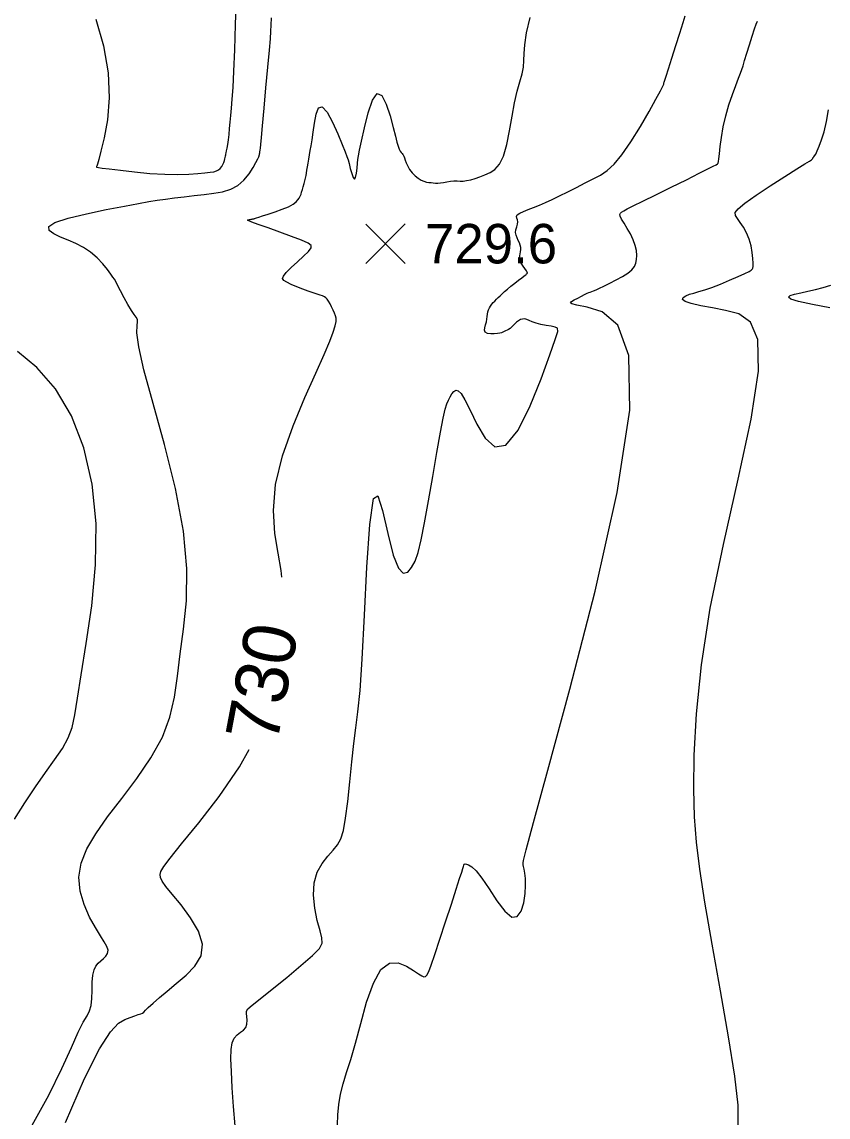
# Model space of a CAD drawing. Extents: x 2566142 to 2571431, y 418755 to 421584.
# Drawn here: x 2569336.6 to 2569642.8, y 419170.9 to 419587 of the extents above; entities that cross this region are included whole.
import ezdxf

# ---------------------------------------------------------------- set-up
doc = ezdxf.new("R2010")
doc.units = 0
for name, color, linetype in [('Contour_ADS_Label_Major', 7, 'Continuous'), ('Contour_ADS_Major', 7, 'Continuous'), ('Contour_ADS_Minor', 7, 'Continuous'), ('Contour_ADS_Spot_Elevation', 7, 'Continuous')]:
    doc.layers.add(name, color=color, linetype=linetype)

# ---------------------------------------------------------------- blocks, each defined once
blk = doc.blocks.new('S750')
at = {"layer": 'Contour_ADS_Spot_Elevation'}
for p, q in [((-0.5, 0.498), (0.5, -0.498)), ((-0.498, -0.5), (0.498, 0.5))]:
    blk.add_line(p, q, dxfattribs=at)

msp = doc.modelspace()

# ---------------------------------------------------------------- linework, layer by layer
at = {"layer": 'Contour_ADS_Major'}
for points in [[(2569449.32, 419554.31), (2569450.68, 419554.75), (2569452.5, 419552.7), (2569454.55, 419548.9), (2569456.55, 419544.45), (2569458.21, 419540.43), (2569459.34, 419537.67), (2569460.03, 419535.9), (2569460.48, 419534.58), (2569460.87, 419533.18), (2569461.34, 419531.34), (2569461.88, 419529.4), (2569462.44, 419527.86), (2569462.94, 419527.24), (2569463.34, 419527.89), (2569463.65, 419529.46), (2569463.88, 419531.42), (2569464.06, 419533.27), (2569464.21, 419534.68), (2569464.44, 419536.12), (2569464.86, 419538.23), (2569465.58, 419541.69), (2569466.69, 419546.79), (2569468.12, 419552.45), (2569469.76, 419557.25), (2569471.51, 419559.75), (2569473.27, 419558.97), (2569474.94, 419555.73), (2569476.42, 419551.27), (2569477.62, 419546.88), (2569478.48, 419543.54), (2569479.07, 419541.25), (2569479.49, 419539.72), (2569479.85, 419538.69), (2569480.23, 419537.92), (2569480.61, 419537.34), (2569480.97, 419536.93), (2569481.25, 419536.64), (2569481.44, 419536.45), (2569481.58, 419536.24), (2569481.72, 419535.92), (2569481.9, 419535.36), (2569482.17, 419534.5), (2569482.57, 419533.39), (2569483.13, 419532.15), (2569483.87, 419530.87), (2569484.82, 419529.65), (2569485.91, 419528.55), (2569487.07, 419527.62), (2569488.21, 419526.9), (2569489.27, 419526.43), (2569490.26, 419526.15), (2569491.17, 419526), (2569492.01, 419525.91), (2569492.82, 419525.83), (2569493.63, 419525.76), (2569494.52, 419525.75), (2569495.55, 419525.82), (2569496.74, 419525.99), (2569498.05, 419526.21), (2569499.39, 419526.42), (2569500.68, 419526.55), (2569501.86, 419526.57), (2569503, 419526.53), (2569504.19, 419526.53), (2569505.52, 419526.67), (2569507.05, 419526.99), (2569508.76, 419527.5), (2569510.59, 419528.14), (2569512.49, 419528.87), (2569514.41, 419529.71), (2569516.26, 419530.95), (2569517.98, 419532.94), (2569519.49, 419536.03), (2569520.74, 419540.41), (2569521.8, 419545.64), (2569522.77, 419551.13), (2569523.74, 419556.28), (2569524.76, 419560.62), (2569525.75, 419564.21), (2569526.58, 419567.22), (2569527.12, 419569.84), (2569527.3, 419572.28), (2569527.35, 419574.95), (2569527.58, 419578.3), (2569528.26, 419582.78), (2569529.64, 419588.64)], [(2569435.34, 419376.06), (2569435.12, 419378.57), (2569433.96, 419385.12), (2569432.72, 419392.67), (2569432.13, 419401.32), (2569432.93, 419411.17), (2569435.62, 419422.15), (2569439.63, 419433.49), (2569444.12, 419444.26), (2569448.25, 419453.52), (2569451.39, 419460.57), (2569453.53, 419465.62), (2569454.89, 419469.12), (2569455.65, 419471.5), (2569455.98, 419473.17), (2569455.99, 419474.38), (2569455.75, 419475.37), (2569455.33, 419476.34), (2569454.81, 419477.47), (2569454.23, 419478.68), (2569453.65, 419479.85), (2569453.09, 419480.86), (2569452.6, 419481.61), (2569452.1, 419482.15), (2569451.54, 419482.55), (2569450.82, 419482.88), (2569449.88, 419483.2), (2569448.69, 419483.58), (2569447.2, 419484.05), (2569445.39, 419484.66), (2569443.27, 419485.45), (2569441.04, 419486.34), (2569438.94, 419487.24), (2569437.22, 419488.06), (2569436.09, 419488.76), (2569435.64, 419489.48), (2569435.93, 419490.41), (2569437.03, 419491.75), (2569438.92, 419493.61), (2569441.23, 419495.77), (2569443.54, 419497.93), (2569445.41, 419499.78), (2569446.44, 419501.1), (2569446.45, 419502.08), (2569445.29, 419502.97), (2569442.82, 419504.05), (2569439.05, 419505.49), (2569434.56, 419507.13), (2569430.09, 419508.74), (2569426.39, 419510.06), (2569423.99, 419510.92), (2569422.74, 419511.39), (2569422.31, 419511.6), (2569422.33, 419511.68), (2569422.53, 419511.75), (2569422.8, 419511.81), (2569423.11, 419511.88), (2569423.42, 419511.94), (2569423.68, 419511.99), (2569423.91, 419512.03), (2569424.12, 419512.07), (2569424.32, 419512.1), (2569424.52, 419512.14), (2569424.71, 419512.18), (2569424.91, 419512.23), (2569425.09, 419512.28), (2569425.31, 419512.36), (2569425.72, 419512.5), (2569426.55, 419512.78), (2569428.01, 419513.25), (2569430.19, 419513.94), (2569432.83, 419514.81), (2569435.51, 419515.78), (2569437.87, 419516.77), (2569439.59, 419517.72), (2569440.74, 419518.58), (2569441.46, 419519.35), (2569441.91, 419520), (2569442.21, 419520.53), (2569442.44, 419521.03), (2569442.64, 419521.58), (2569442.86, 419522.3), (2569443.14, 419523.25), (2569443.46, 419524.37), (2569443.79, 419525.53), (2569444.08, 419526.66), (2569444.32, 419527.66), (2569444.53, 419528.59), (2569444.71, 419529.55), (2569444.89, 419530.63), (2569445.09, 419531.89), (2569445.3, 419533.3), (2569445.54, 419534.83), (2569445.81, 419536.42), (2569446.1, 419538.07), (2569446.43, 419539.93), (2569446.79, 419542.2), (2569447.21, 419545.08), (2569447.7, 419548.57), (2569448.37, 419551.95), (2569449.32, 419554.31)], [(2569353.19, 419168.77), (2569360.43, 419185.57), (2569366.08, 419196.85), (2569370.26, 419203.33), (2569373.35, 419206.52), (2569375.75, 419207.91), (2569377.77, 419208.77), (2569379.46, 419209.38), (2569380.8, 419209.82), (2569381.75, 419210.14), (2569382.36, 419210.42), (2569382.86, 419210.8), (2569383.52, 419211.45), (2569384.63, 419212.52), (2569386.41, 419214.14), (2569388.84, 419216.26), (2569391.81, 419218.79), (2569395.24, 419221.65), (2569398.94, 419224.77), (2569402.3, 419228.23), (2569404.64, 419232.12), (2569405.26, 419236.55), (2569403.73, 419241.51), (2569400.69, 419246.65), (2569397.04, 419251.48), (2569393.68, 419255.55), (2569391.33, 419258.51), (2569389.93, 419260.55), (2569389.28, 419261.97), (2569389.13, 419263.06), (2569389.38, 419264.19), (2569390.46, 419266.03), (2569392.91, 419269.28), (2569397.26, 419274.68), (2569403.78, 419282.67), (2569411.51, 419292.69), (2569419.23, 419303.91), (2569422.94, 419310.56)]]:
    msp.add_lwpolyline(points, dxfattribs=at)
at = {"layer": 'Contour_ADS_Minor'}
for points in [[(2569364.71, 419587.98), (2569367.63, 419577.85), (2569369.42, 419567.58), (2569369.79, 419558.11), (2569369.12, 419549.82), (2569367.9, 419542.99), (2569366.65, 419537.88), (2569365.79, 419534.65), (2569365.3, 419532.93), (2569365.08, 419532.23), (2569365, 419532.04), (2569364.98, 419531.95), (2569364.99, 419531.89), (2569365.01, 419531.84), (2569365.04, 419531.79), (2569365.15, 419531.75), (2569365.68, 419531.65), (2569367.08, 419531.46), (2569369.78, 419531.11), (2569374.03, 419530.59), (2569379.39, 419529.99), (2569385.21, 419529.44), (2569390.86, 419529.07), (2569395.82, 419528.98), (2569400, 419529.1), (2569403.41, 419529.35), (2569406.1, 419529.62), (2569408.09, 419529.85), (2569409.53, 419530.07), (2569410.56, 419530.35), (2569411.32, 419530.75), (2569411.96, 419531.31), (2569412.49, 419532), (2569412.93, 419532.76), (2569413.27, 419533.53), (2569413.53, 419534.27), (2569413.72, 419534.93), (2569413.85, 419535.49), (2569413.94, 419535.91), (2569413.99, 419536.19), (2569414.04, 419536.41), (2569414.1, 419536.71), (2569414.19, 419537.2), (2569414.35, 419537.97), (2569414.55, 419539.06), (2569414.78, 419540.46), (2569415.02, 419542.17), (2569415.27, 419544.18), (2569415.51, 419546.44), (2569415.76, 419548.9), (2569416, 419551.48), (2569416.25, 419554.23), (2569416.51, 419557.59), (2569416.79, 419562.08), (2569417.09, 419568.25), (2569417.43, 419576.4), (2569417.77, 419586), (2569418.1, 419596.29)], [(2569380.55, 419473.08), (2569380.47, 419473.97), (2569380.05, 419474.78), (2569379.29, 419475.8), (2569378.22, 419477.33), (2569376.87, 419479.55), (2569375.42, 419482.18), (2569374.05, 419484.77), (2569372.95, 419486.9), (2569372.24, 419488.3), (2569371.73, 419489.22), (2569371.2, 419490.05), (2569370.38, 419491.19), (2569369.08, 419492.92), (2569367.33, 419495.08), (2569365.18, 419497.38), (2569362.71, 419499.52), (2569360, 419501.3), (2569357.13, 419502.76), (2569354.21, 419504.03), (2569351.33, 419505.24), (2569348.7, 419506.48), (2569346.96, 419507.79), (2569346.85, 419509.21), (2569349.13, 419510.75), (2569354.19, 419512.41), (2569361.12, 419514.09), (2569368.65, 419515.65), (2569375.54, 419516.98), (2569380.84, 419517.98), (2569384.81, 419518.7), (2569388.05, 419519.24), (2569391.15, 419519.69), (2569394.57, 419520.12), (2569398.27, 419520.55), (2569402.1, 419520.97), (2569405.89, 419521.4), (2569409.5, 419521.85), (2569412.86, 419522.46), (2569415.93, 419523.42), (2569418.64, 419524.87), (2569420.96, 419526.91), (2569422.88, 419529.28), (2569424.39, 419531.61), (2569425.48, 419533.58), (2569426.17, 419534.91), (2569426.55, 419535.68), (2569426.7, 419536.06), (2569426.75, 419536.22), (2569426.76, 419536.31), (2569426.78, 419536.38), (2569426.8, 419536.48), (2569426.83, 419536.63), (2569426.88, 419536.88), (2569426.94, 419537.22), (2569427.01, 419537.67), (2569427.09, 419538.21), (2569427.18, 419538.95), (2569427.32, 419540.37), (2569427.57, 419543.04), (2569427.98, 419547.55), (2569428.59, 419554.17), (2569429.3, 419561.97), (2569430.01, 419569.73), (2569430.59, 419576.22), (2569430.97, 419580.58), (2569431.18, 419583.42), (2569431.29, 419585.73), (2569431.36, 419588.47)], [(2569586.47, 419582.74), (2569587.72, 419586.72), (2569588.56, 419589.32)], [(2569568.82, 419517.08), (2569572.39, 419518.86), (2569577.4, 419521.34), (2569583.2, 419524.2), (2569588.96, 419527.04), (2569593.83, 419529.45), (2569597.18, 419531.1), (2569599.19, 419532.12), (2569600.25, 419532.7), (2569600.75, 419533.04), (2569601.02, 419533.37), (2569601.18, 419533.93), (2569601.32, 419535), (2569601.51, 419536.82), (2569601.82, 419539.58), (2569602.3, 419543.09), (2569602.99, 419547.1), (2569603.93, 419551.33), (2569605.13, 419555.52), (2569606.44, 419559.44), (2569607.71, 419562.87), (2569608.76, 419565.58), (2569609.49, 419567.47), (2569610, 419568.9), (2569610.48, 419570.35), (2569611.08, 419572.3), (2569611.92, 419575.07), (2569612.93, 419578.33), (2569613.95, 419581.57), (2569614.84, 419584.3), (2569615.49, 419586.14), (2569615.94, 419587.25)], [(2569522.65, 419471.08), (2569522.07, 419470.55), (2569521.47, 419470.15), (2569520.86, 419469.83), (2569520.27, 419469.58), (2569519.73, 419469.36), (2569519.26, 419469.13), (2569518.75, 419468.91), (2569518.1, 419468.7), (2569517.2, 419468.54), (2569515.99, 419468.44), (2569514.66, 419468.45), (2569513.45, 419468.65), (2569512.6, 419469.11), (2569512.28, 419469.85), (2569512.38, 419470.81), (2569512.69, 419471.89), (2569513.03, 419473.01), (2569513.24, 419474.07), (2569513.36, 419475.07), (2569513.45, 419476), (2569513.58, 419476.85), (2569513.81, 419477.63), (2569514.15, 419478.35), (2569514.58, 419479.03), (2569515.08, 419479.68), (2569515.64, 419480.31), (2569516.24, 419480.94), (2569516.88, 419481.58), (2569517.54, 419482.24), (2569518.22, 419482.93), (2569518.98, 419483.68), (2569519.88, 419484.53), (2569521, 419485.5), (2569522.36, 419486.61), (2569523.83, 419487.77), (2569525.24, 419488.85), (2569526.42, 419489.76), (2569527.24, 419490.4), (2569527.76, 419490.81), (2569528.08, 419491.07), (2569528.29, 419491.23), (2569528.47, 419491.38), (2569528.57, 419491.58), (2569528.52, 419491.91), (2569528.23, 419492.45), (2569527.67, 419493.25), (2569526.96, 419494.23), (2569526.28, 419495.29), (2569525.79, 419496.32), (2569525.6, 419497.26), (2569525.66, 419498.1), (2569525.84, 419498.89), (2569526.02, 419499.67), (2569526.1, 419500.46), (2569526.07, 419501.27), (2569525.9, 419502.12), (2569525.58, 419503.01), (2569525.14, 419503.93), (2569524.67, 419504.9), (2569524.29, 419505.91), (2569524.13, 419506.96), (2569524.26, 419508.04), (2569524.57, 419509.11), (2569524.86, 419510.12), (2569524.98, 419511.03), (2569524.81, 419511.79), (2569524.54, 419512.45), (2569524.44, 419513.05), (2569524.75, 419513.65), (2569525.66, 419514.27), (2569527.1, 419514.95), (2569528.92, 419515.69), (2569530.97, 419516.49), (2569533.14, 419517.38), (2569535.47, 419518.39), (2569538.01, 419519.55), (2569540.83, 419520.9), (2569543.96, 419522.45), (2569547.25, 419524.12), (2569550.52, 419525.79), (2569553.58, 419527.35), (2569556.32, 419528.79), (2569558.9, 419530.48), (2569561.55, 419532.88), (2569564.52, 419536.46), (2569567.93, 419541.45), (2569571.49, 419547.22), (2569574.78, 419552.91), (2569577.41, 419557.63), (2569579.1, 419560.76), (2569579.98, 419562.53), (2569580.35, 419563.38), (2569580.46, 419563.77), (2569580.56, 419564.14), (2569580.81, 419564.89), (2569581.3, 419566.41), (2569582.16, 419569.1), (2569583.44, 419573.14), (2569584.96, 419577.96), (2569586.47, 419582.74)], [(2569614.06, 419493.12), (2569614.21, 419493.43), (2569614.33, 419494.1), (2569614.37, 419495.29), (2569614.27, 419497.1), (2569614, 419499.37), (2569613.52, 419501.9), (2569612.78, 419504.45), (2569611.78, 419506.83), (2569610.63, 419508.96), (2569609.45, 419510.79), (2569608.39, 419512.27), (2569607.64, 419513.41), (2569607.56, 419514.52), (2569608.6, 419515.96), (2569611.18, 419518.09), (2569615.5, 419521.13), (2569620.85, 419524.68), (2569626.3, 419528.2), (2569630.91, 419531.12), (2569633.97, 419533.05), (2569635.69, 419534.11), (2569636.47, 419534.61), (2569636.74, 419534.81), (2569636.87, 419534.96), (2569636.95, 419535.12), (2569637.03, 419535.28), (2569637.15, 419535.46), (2569637.34, 419535.68), (2569637.64, 419536.08), (2569638.08, 419536.79), (2569638.67, 419537.97), (2569639.44, 419539.73), (2569640.32, 419542.15), (2569641.25, 419545.25), (2569642.14, 419549.08), (2569642.95, 419553.63)], [(2569461.52, 419192.74), (2569463.31, 419198.92), (2569465.31, 419206.49), (2569467.55, 419214.51), (2569470.09, 419221.76), (2569472.98, 419227.01), (2569476.21, 419229.4), (2569479.54, 419229.5), (2569482.68, 419228.26), (2569485.3, 419226.6), (2569487.2, 419225.3), (2569488.48, 419224.5), (2569489.32, 419224.15), (2569489.92, 419224.24), (2569490.46, 419224.8), (2569491.11, 419226.15), (2569492.03, 419228.65), (2569493.4, 419232.7), (2569495.31, 419238.43), (2569497.52, 419245.11), (2569499.72, 419251.78), (2569501.58, 419257.48), (2569502.87, 419261.48), (2569503.66, 419263.96), (2569504.09, 419265.38), (2569504.31, 419266.15), (2569504.45, 419266.64), (2569504.62, 419266.94), (2569504.92, 419267.06), (2569505.43, 419267.02), (2569506.26, 419266.77), (2569507.47, 419266.02), (2569509.13, 419264.44), (2569511.32, 419261.67), (2569514.03, 419257.6), (2569517.03, 419253.06), (2569520, 419249.13), (2569522.65, 419246.87), (2569524.72, 419247.04), (2569526.22, 419249.13), (2569527.21, 419252.33), (2569527.75, 419255.83), (2569527.91, 419258.93), (2569527.81, 419261.51), (2569527.57, 419263.57), (2569527.31, 419265.08), (2569527.13, 419266.1), (2569527.03, 419266.73), (2569526.99, 419267.13), (2569526.98, 419267.45), (2569527.12, 419268.35), (2569528.16, 419272.44), (2569530.95, 419282.85), (2569536.37, 419302.69), (2569544.77, 419333.53), (2569554.33, 419370.74), (2569562.7, 419408.13), (2569567.51, 419439.53), (2569567.16, 419460.25), (2569562.96, 419471.72), (2569556.97, 419476.86), (2569551.24, 419478.59), (2569547.4, 419479.38), (2569545.44, 419479.88), (2569544.9, 419480.26), (2569545.35, 419480.7), (2569546.36, 419481.33), (2569547.69, 419482.08), (2569549.09, 419482.83), (2569550.34, 419483.46), (2569551.26, 419483.89), (2569551.92, 419484.16), (2569552.47, 419484.35), (2569553.02, 419484.55), (2569553.71, 419484.82), (2569554.65, 419485.23), (2569555.92, 419485.82), (2569557.64, 419486.64), (2569559.84, 419487.7), (2569562.3, 419488.94), (2569564.7, 419490.26), (2569566.77, 419491.57), (2569568.27, 419492.8), (2569569.25, 419494), (2569569.81, 419495.26), (2569570.09, 419496.67), (2569570.15, 419498.29), (2569569.99, 419500.1), (2569569.56, 419502.09), (2569568.8, 419504.2), (2569567.72, 419506.4), (2569566.49, 419508.55), (2569565.29, 419510.48), (2569564.35, 419512.04), (2569563.82, 419513.12), (2569563.68, 419513.83), (2569563.89, 419514.31), (2569564.38, 419514.71), (2569565.16, 419515.19), (2569566.52, 419515.92), (2569568.82, 419517.08)], [(2569608.7, 419167.96), (2569608.65, 419175.47), (2569607.33, 419186.42), (2569604.94, 419201.42), (2569601.91, 419218.87), (2569598.77, 419236.63), (2569596, 419252.55), (2569594.02, 419265.12), (2569592.77, 419275.37), (2569592.1, 419284.94), (2569591.86, 419295.5), (2569591.98, 419308.44), (2569592.77, 419324.14), (2569594.66, 419342.71), (2569598.05, 419364.26), (2569603.07, 419388.46), (2569608.68, 419413.23), (2569613.53, 419436.02), (2569616.32, 419454.31), (2569616.07, 419466.28), (2569613.31, 419472.96), (2569608.95, 419476.07), (2569603.87, 419477.36), (2569598.89, 419478.29), (2569594.44, 419479.14), (2569590.85, 419479.95), (2569588.47, 419480.73), (2569587.5, 419481.5), (2569587.71, 419482.23), (2569588.73, 419482.9), (2569590.21, 419483.49), (2569591.85, 419483.98), (2569593.73, 419484.49), (2569595.96, 419485.14), (2569598.68, 419486.07), (2569601.94, 419487.34), (2569605.39, 419488.8), (2569608.61, 419490.23), (2569611.17, 419491.42), (2569612.77, 419492.21), (2569613.56, 419492.65), (2569613.86, 419492.87), (2569613.94, 419492.98), (2569614.06, 419493.12)], [(2569643.44, 419478.4), (2569636.81, 419479.65), (2569631.59, 419480.77), (2569628.63, 419481.67), (2569627.73, 419482.39), (2569628.37, 419482.98), (2569630.07, 419483.51), (2569632.4, 419484.05), (2569635.11, 419484.63), (2569638.03, 419485.3), (2569640.98, 419486.08), (2569643.78, 419487.01)], [(2569339.91, 419166.63), (2569346.8, 419179.2), (2569351.83, 419189.4), (2569355.42, 419197.33), (2569358, 419203.1), (2569359.94, 419206.91), (2569361.37, 419209.39), (2569362.34, 419211.27), (2569362.92, 419213.26), (2569363.18, 419215.91), (2569363.26, 419219), (2569363.33, 419222.1), (2569363.53, 419224.82), (2569364, 419226.85), (2569364.7, 419228.28), (2569365.58, 419229.33), (2569366.58, 419230.21), (2569367.62, 419231.09), (2569368.54, 419232.04), (2569369.18, 419233.09), (2569369.35, 419234.28), (2569368.91, 419235.66), (2569367.91, 419237.42), (2569366.42, 419239.75), (2569364.52, 419242.86), (2569362.35, 419246.87), (2569360.29, 419251.6), (2569358.78, 419256.76), (2569358.27, 419262.08), (2569359.11, 419267.38), (2569361.28, 419272.79), (2569364.66, 419278.56), (2569369.15, 419284.9), (2569374.53, 419291.97), (2569380.23, 419299.56), (2569385.6, 419307.41), (2569389.96, 419315.23), (2569392.86, 419322.84), (2569394.61, 419330.44), (2569395.74, 419338.35), (2569396.77, 419346.87), (2569398.02, 419356.32), (2569399.07, 419367.02), (2569399.29, 419379.32), (2569398.04, 419393.54), (2569394.97, 419409.69), (2569390.79, 419426.41), (2569386.46, 419442.02), (2569382.96, 419454.81), (2569381.01, 419463.56), (2569380.32, 419468.84), (2569380.35, 419471.67), (2569380.55, 419473.08)], [(2569416.52, 419199.14), (2569417.26, 419200.91), (2569418.35, 419202.15), (2569419.6, 419203.1), (2569420.79, 419203.96), (2569421.68, 419204.96), (2569422.1, 419206.23), (2569422.16, 419207.66), (2569422.02, 419209.05), (2569421.86, 419210.21), (2569421.88, 419211.07), (2569422.47, 419211.97), (2569424.06, 419213.39), (2569427.06, 419215.81), (2569431.67, 419219.49), (2569437.17, 419223.93), (2569442.6, 419228.42), (2569446.98, 419232.24), (2569449.6, 419234.93), (2569450.65, 419236.93), (2569450.58, 419238.94), (2569449.83, 419241.65), (2569448.81, 419245.53), (2569447.88, 419250.24), (2569447.36, 419255.23), (2569447.59, 419259.95), (2569448.78, 419263.95), (2569450.66, 419267.25), (2569452.82, 419269.99), (2569454.87, 419272.28), (2569456.5, 419274.34), (2569457.75, 419276.66), (2569458.73, 419279.82), (2569459.57, 419284.42), (2569460.37, 419290.77), (2569461.15, 419298.22), (2569461.92, 419305.89), (2569462.69, 419312.88), (2569463.46, 419318.73), (2569464.23, 419324.81), (2569465.02, 419332.93), (2569465.83, 419344.88), (2569466.68, 419361.53), (2569467.62, 419379.87), (2569468.74, 419395.98), (2569470.1, 419405.89), (2569471.75, 419406.91), (2569473.62, 419401.33), (2569475.61, 419392.66), (2569477.63, 419384.44), (2569479.59, 419379.45), (2569481.44, 419377.56), (2569483.13, 419377.91), (2569484.63, 419379.63), (2569485.92, 419382.07), (2569487.09, 419385.44), (2569488.26, 419390.14), (2569489.56, 419396.61), (2569491.07, 419404.98), (2569492.67, 419414.32), (2569494.21, 419423.43), (2569495.56, 419431.1), (2569496.59, 419436.44), (2569497.37, 419439.8), (2569498, 419441.85), (2569498.58, 419443.26), (2569499.21, 419444.56), (2569499.89, 419445.73), (2569500.64, 419446.61), (2569501.44, 419447.05), (2569502.33, 419446.85), (2569503.43, 419445.74), (2569504.89, 419443.4), (2569506.84, 419439.51), (2569509.41, 419434.13), (2569512.56, 419428.82), (2569516.27, 419425.51), (2569520.46, 419426.12), (2569525.04, 419431.88), (2569529.61, 419441.11), (2569533.77, 419451.42), (2569537.06, 419460.43), (2569539.15, 419466.29), (2569540.1, 419469.39), (2569540.06, 419470.66), (2569539.2, 419471.05), (2569537.68, 419471.32), (2569535.76, 419471.64), (2569533.74, 419472.02), (2569531.88, 419472.47), (2569530.42, 419472.98), (2569529.29, 419473.48), (2569528.37, 419473.88), (2569527.56, 419474.11), (2569526.75, 419474.09), (2569525.95, 419473.86), (2569525.18, 419473.46), (2569524.46, 419472.94), (2569523.82, 419472.33), (2569523.22, 419471.69), (2569522.65, 419471.08)], [(2569333.86, 419284.02), (2569337.78, 419290.32), (2569341.78, 419296.39), (2569345.59, 419301.8), (2569349.04, 419306.59), (2569351.98, 419310.93), (2569354.23, 419314.95), (2569355.72, 419318.95), (2569356.77, 419323.67), (2569357.78, 419330.03), (2569359.14, 419338.9), (2569361.08, 419350.86), (2569363.12, 419365.16), (2569364.59, 419380.71), (2569364.83, 419396.44), (2569363.32, 419411.39), (2569360.11, 419425.12), (2569355.39, 419437.27), (2569349.36, 419447.51), (2569342.32, 419455.62), (2569334.98, 419461.78)], [(2569417.56, 419167.52), (2569416.99, 419174.85), (2569416.51, 419181.96), (2569416.17, 419188.19), (2569416.02, 419193.03), (2569416.12, 419196.59), (2569416.52, 419199.14)], [(2569456.52, 419167.98), (2569456.63, 419171.74), (2569456.99, 419175.69), (2569457.66, 419179.65), (2569458.65, 419183.55), (2569459.95, 419187.77), (2569461.52, 419192.74)]]:
    msp.add_lwpolyline(points, dxfattribs=at)

# ---------------------------------------------------------------- block references
at = {"layer": 'Contour_ADS_Spot_Elevation', "xscale": 15, "yscale": 15}
msp.add_blockref('S750', (2569474.68, 419502.72), dxfattribs=at)

# ---------------------------------------------------------------- texts
at = {"layer": 'Contour_ADS_Label_Major'}
msp.add_text('730', height=20, rotation=79.2825, dxfattribs=at).set_placement((2569433.44, 419312.25))
at = {"layer": 'Contour_ADS_Spot_Elevation'}
msp.add_text('729.6', height=15, dxfattribs=at).set_placement((2569489.68, 419495.22))

doc.saveas('drawing.dxf')
